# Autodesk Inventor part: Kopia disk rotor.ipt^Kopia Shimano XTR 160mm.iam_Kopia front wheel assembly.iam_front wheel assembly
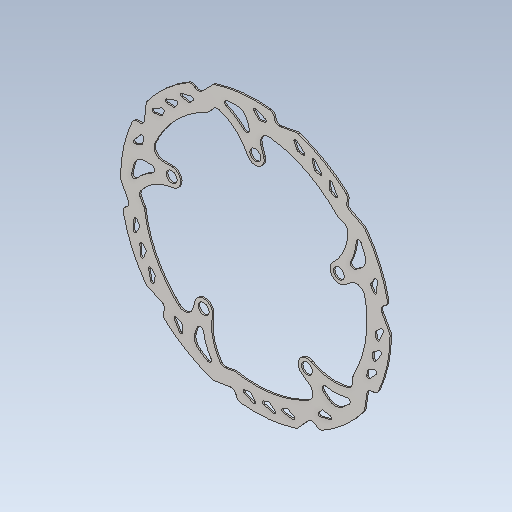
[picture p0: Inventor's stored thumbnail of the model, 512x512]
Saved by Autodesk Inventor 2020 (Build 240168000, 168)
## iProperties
Created: 2017-09
Part Number: Kopia disk rotor.ipt^Kopia Shimano XTR 160mm.iam_Kopia front wheel assembly.iam_front wheel assembly
Material: Ogólny
Document SubType Name: Modeling
Designer: Tomasz
Density: 1 g/cm^3
Appearance: Domyślna
Sending System: SolidWorks 2017
Last Author: Tomasz
Last Saved: 2017-09-11
Author: Tomasz
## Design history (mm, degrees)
feature "disk rotor.ipt"
node "Bryła1"
